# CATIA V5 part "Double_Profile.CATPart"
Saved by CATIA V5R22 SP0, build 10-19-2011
Part number: Double_Profile
Material "Acier": density 7860 kg/m3, Young's modulus 2e+11 Pa, Poisson ratio 0.266, thermal expansion 1.17e-05 1/K
Bounding box of the stored display mesh (mm): x -10 to 10, y -20 to 20, z 0 to 1000
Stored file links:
  U:\S9A\PER\CAO\Assemblage\Cadre\Chariot_X\Double_Profile.CATPart
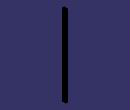
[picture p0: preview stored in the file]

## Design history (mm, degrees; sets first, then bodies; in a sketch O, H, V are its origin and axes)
Body1 (main body), material "Acier"
  Sketch1 on xy-plane, origin (0, 0, 0), H (1, 0, 0), V (0, 1, 0)
    line L1 (10, 20) -> (10, -20)
    line L2 (10, -20) -> (-10, -20)
    line L3 (-10, -20) -> (-10, 20)
    line L4 (-10, 20) -> (10, 20)
    length L2 = 20
    length L1 = 40
    vertical: L1 V, L3 V
    horizontal: L2 H, L4 H
    equidistance: L1 L3 O, L2 L4 O
  Pad1: profile Sketch1, direction (0, 0, 1), length 1000
  Sketch2 on end face of Pad1, origin (0, 0, 1000), H (1, 0, 0), V (0, 1, 0)
    line L1 (4, 5) -> (4, -5)
    line L2 (4, -5) -> (-4, -5)
    line L3 (-4, -5) -> (-4, 5)
    line L4 (-4, 5) -> (4, 5)
    length L1 = 10
    length L2 = 8
    vertical: L1 V, L3 V
    horizontal: L2 H, L4 H
    equidistance: L1 L3 O, L2 L4 O
  Pocket1: profile Sketch2, direction (0, 0, -1), length 1000
  Sketch3 on end face of Pad1, origin (0, 0, 1000), H (1, 0, 0), V (0, 1, 0)
    line L1 (-4, -15) -> (4, -15)
    line L2 (4, -15) -> (4, -20)
    line L3 (4, -20) -> (-4, -20)
    line L4 (-4, -20) -> (-4, -15)
    reference projected line E1 (-10, -20) -> (10, -20) from edge [face of Pad1 from Sketch1.L2 | end face of Pad1]
    reference projected line E2 (10, -20) -> (10, 20) from edge [face of Pad1 from Sketch1.L1 | end face of Pad1]
    length L2 = 5
    length L3 = 8
    distance L2 E2 = 6
    horizontal: L1 H, L3 H
    vertical: L2 V, L4 V
    coincidence: E1 L3
  Pocket2: profile Sketch3, direction (0, 0, -1), length 1000
  RectPattern1: of Pocket2, direction 1 instances 1, spacing 35, along end face of Pad1, direction 2 instances 2, spacing 35, along end face of Pad1
  Sketch4 on end face of Pad1, origin (0, 0, 1000), H (1, 0, 0), V (0, 1, 0)
    line L1 (5, 14) -> (10, 14)
    line L2 (10, 14) -> (10, 6)
    line L3 (10, 6) -> (5, 6)
    line L4 (5, 6) -> (5, 14)
    reference projected line E1 (10, -20) -> (10, 20) from edge [face of Pad1 from Sketch1.L1 | end face of Pad1]
    reference projected line E2 (10, 20) -> (-10, 20) from edge [face of Pad1 from Sketch1.L4 | end face of Pad1]
    length L2 = 8
    length L3 = 5
    distance L1 E2 = 6
    horizontal: L1 H, L3 H
    vertical: L2 V, L4 V
    coincidence: L2 E1
  Pocket3: profile Sketch4, direction (0, 0, -1), length 1000
  RectPattern2: of Pocket3, direction 1 instances 2, spacing 15, along end face of Pad1 reversed, direction 2 instances 2, spacing 20, along end face of Pad1 reversed
  Chamfer1: length 1, angle 45, on edge [face of Pad1 from Sketch1.L3 | face of RectPattern2] (x2); edge [face of RectPattern2 | face of Pad1 from Sketch1.L3] (x2); edge [face of Pad1 from Sketch1.L1 | face of Pocket3 from Sketch4.L3]; edge [face of Pocket3 from Sketch4.L1 | face of Pad1 from Sketch1.L1]; edge [face of Pad1 from Sketch1.L1 | face of RectPattern2]; edge [face of RectPattern2 | face of Pad1 from Sketch1.L1]; edge [face of Pad1 from Sketch1.L4 | face of RectPattern1]; edge [face of RectPattern1 | face of Pad1 from Sketch1.L4]; edge [face of Pad1 from Sketch1.L2 | face of Pocket2 from Sketch3.L4]; edge [face of Pocket2 from Sketch3.L2 | face of Pad1 from Sketch1.L2]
